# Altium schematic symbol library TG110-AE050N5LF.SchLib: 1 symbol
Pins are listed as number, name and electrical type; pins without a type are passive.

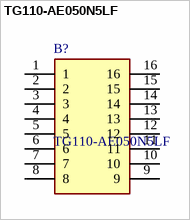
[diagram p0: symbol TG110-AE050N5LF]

## TG110-AE050N5LF
designator B?
Audio Transformers / Signal Transformers 10/100BASE-TX SMD AEC-Q200 16P 1-Port; Manufacturer_Name: Halo Electronics; Geometry.Height: 6.35mm
footprint SOIC127P953X635-16N
pins: 1, 2, 3, 4, 5, 6, 7, 8, 9, 10, 11, 12, 13, 14, 15, 16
